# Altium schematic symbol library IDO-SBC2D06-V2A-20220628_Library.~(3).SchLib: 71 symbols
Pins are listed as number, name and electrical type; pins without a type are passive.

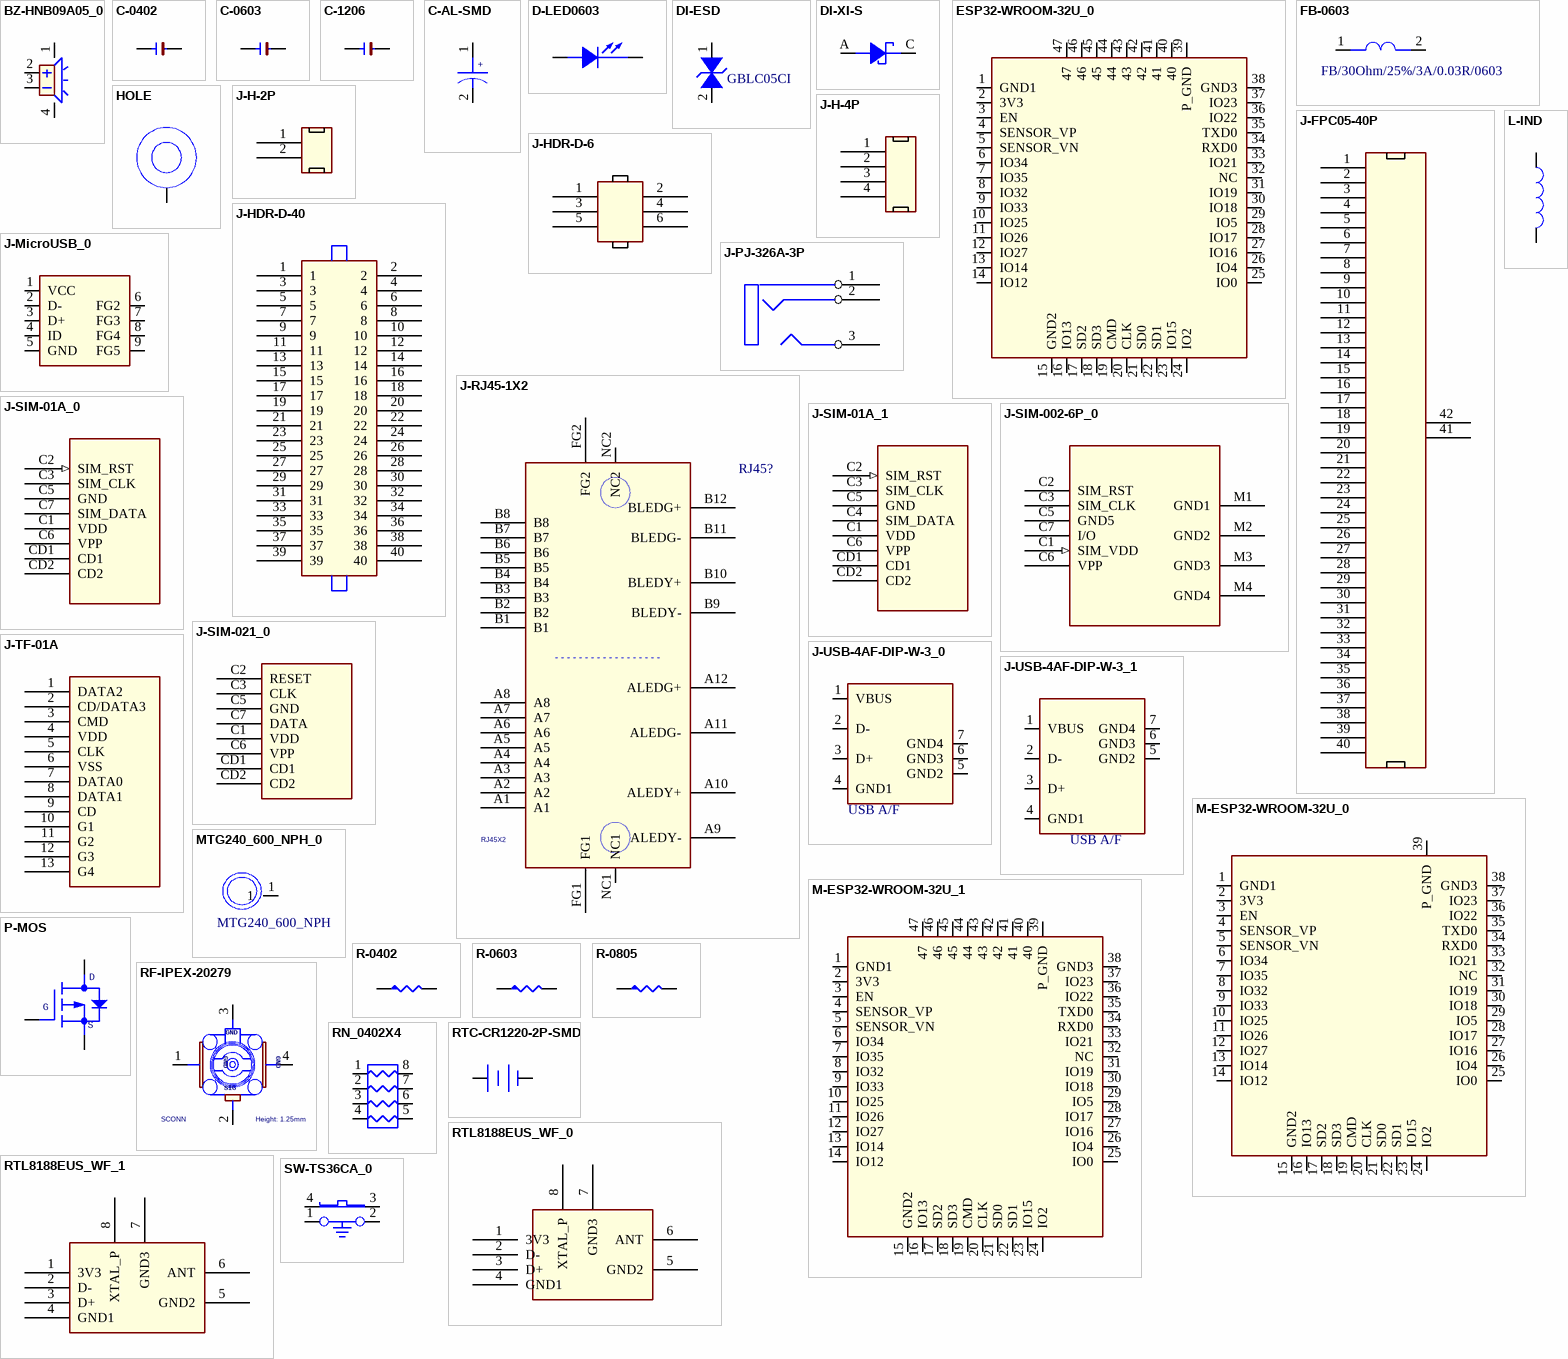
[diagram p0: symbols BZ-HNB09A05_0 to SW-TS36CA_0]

## BZ-HNB09A05_0
designator BUZZER?
Altium-Right: 20; Altium-Bottom: 30
pins: 1, 2 +, 3 -, 4

## C-0402
designator C?
Altium-Right: 10; Altium-Bottom: 20
footprint 1206
pins: 1, 2

## C-0603
designator C?
Altium-Right: 10; Altium-Bottom: 20
footprint 1206
pins: 1, 2

## C-1206
designator C?
Altium-Right: 10; Altium-Bottom: 20
footprint 1206
pins: 1, 2

## C-AL-SMD
designator CP?
Altium-Right: 20
pins: 1, 2

## D-LED0603
designator LED?
Altium-Right: 40; Altium-Bottom: 20
pins: A ANODE, C CATHODE

## DI-ESD
designator T?, comment GBLC05CI
ESD 0402; Manufacturer: INPAQ; Manufacture P/N: MLVG04021R0UV18; Part Number: EB3.1R0UV18402A; PN Type: Varistor; Altium-Right: 20
pins: 1 I/O2, 2 I/O1

## DI-XI-S
designator D?
CLASS: IC; Altium-Right: 30; Altium-Bottom: 20
pins: A, C

## ESP32-WROOM-32U_0
designator U?
Altium-Right: 170; Altium-Bottom: 200
pins: 1 GND1, 2 3V3, 3 EN, 4 SENSOR_VP, 5 SENSOR_VN, 6 IO34, 7 IO35, 8 IO32, 9 IO33, 10 IO25, 11 IO26, 12 IO27, 13 IO14, 14 IO12, 15 GND2, 16 IO13, 17 SD2, 18 SD3, 19 CMD, 20 CLK, 21 SD0, 22 SD1, 23 IO15, 24 IO2, 25 IO0, 26 IO4, 27 IO16, 28 IO17, 29 IO5, 30 IO18, 31 IO19, 32 NC, 33 IO21, 34 RXD0, 35 TXD0, 36 IO22, 37 IO23, 38 GND3, 39 P_GND, 40, 41, 42, 43, 44, 45, 46, 47

## FB-0603
designator FB?, comment FB/30Ohm/25%/3A/0.03R/0603
SMD Multilayer Ferrite Chip Bead,3A,30Ohm,0.03R; Part Number: EL4.300Y060300A; Manufacture P/N: PZ1608D300-3R0TF; Manufacture2 P/N: PBY160808T-400Y-N; Manufacturer: SUNLORD; PN Type: SMD FERRITE BEAD; Altium-Right: 40; Altium-Bottom: 20
pins: 1, 2

## HOLE
designator H?  (value not drawn)
Altium-Right: 40
pins: 1

## J-FPC05-40P
designator J?
Altium-Right: 40; Altium-Bottom: 410
pins: 1, 2, 3, 4, 5, 6, 7, 8, 9, 10, 11, 12, 13, 14, 15, 16, 17, 18, 19, 20, 21, 22, 23, 24, 25, 26, 27, 28, 29, 30, 31, 32, 33, 34, 35, 36, 37, 38, 39, 40, 41, 42

## J-H-2P
designator J?
Altium-Right: 20; Altium-Bottom: 30
pins: 1, 2

## J-H-4P
designator J?
Altium-Right: 20; Altium-Bottom: 50
pins: 1, 2, 3, 4

## J-HDR-D-6
designator J?
Altium-Right: 30; Altium-Bottom: 60
pins: 1, 2, 3, 4, 5, 6

## J-HDR-D-40
designator J?
Altium-Right: 50; Altium-Bottom: 230
pins: 1, 2, 3, 4, 5, 6, 7, 8, 9, 10, 11, 12, 13, 14, 15, 16, 17, 18, 19, 20, 21, 22, 23, 24, 25, 26, 27, 28, 29, 30, 31, 32, 33, 34, 35, 36, 37, 38, 39, 40

## J-MicroUSB_0
designator CN?  (value not drawn)
MicroUSB; Altium-Right: 60
pins: 1 VCC (power), 2 D- (power), 3 D+ (power), 4 ID (io), 5 GND (power), 6 FG2 (power), 7 FG3 (power), 8 FG4 (power), 9 FG5

## J-PJ-326A-3P
designator AU?
P/N: 182K00300S; Altium-Right: 60
pins: 1 COM, 2 L, 3 R

## J-RJ45-1X2
designator RJ45?, comment RJ45X2
Altium-Right: 110; Altium-Bottom: 270
pins: A1, A2, A3, A4, A5, A6, A7, A8, A9 ALEDY-, A10 ALEDY+, A11 ALEDG-, A12 ALEDG+, B1, B2, B3, B4, B5, B6, B7, B8, B9 BLEDY-, B10 BLEDY+, B11 BLEDG-, B12 BLEDG+, FG1, FG2, NC1, NC2

## J-SIM-01A_0
designator J?
Altium-Right: 60; Altium-Bottom: 110
pins: C1 VDD, C2 SIM_RST (in), C3 SIM_CLK, C5 GND, C6 VPP, C7 SIM_DATA, CD1, CD2

## J-SIM-01A_1
designator J?
Altium-Right: 60; Altium-Bottom: 110
pins: C1 VDD, C2 SIM_RST (in), C3 SIM_CLK, C4 SIM_DATA, C5 GND, C6 VPP, CD1, CD2

## J-SIM-002-6P_0
designator SIM?
Altium-Right: 100; Altium-Bottom: 120
pins: C1 SIM_VDD (in), C2 SIM_RST, C3 SIM_CLK, C5 GND5, C6 VPP, C7 I/O, M1 GND1, M2 GND2, M3 GND3, M4 GND4

## J-SIM-021_0
designator J?
Altium-Right: 60; Altium-Bottom: 90
pins: C1 VDD, C2 RESET, C3 CLK, C5 GND, C6 VPP, C7 DATA, CD1, CD2

## J-TF-01A
designator J?
Altium-Right: 60; Altium-Bottom: 140
pins: 1 DATA2, 2 CD/DATA3, 3 CMD, 4 VDD, 5 CLK, 6 VSS, 7 DATA0, 8 DATA1, 9 CD, 10 G1, 11 G2, 12 G3, 13 G4

## J-USB-4AF-DIP-W-3_0
designator USB?, comment USB A/F
micro USB连接器; Altium-Right: 70; Altium-Bottom: 80
pins: 1 VBUS (power), 2 D-, 3 D+, 4 GND1 (power), 5 GND2, 6 GND3, 7 GND4

## J-USB-4AF-DIP-W-3_1
designator USB?, comment USB A/F
micro USB连接器; Altium-Right: 70; Altium-Bottom: 90
pins: 1 VBUS (power), 2 D-, 3 D+, 4 GND1 (power), 5 GND2, 6 GND3, 7 GND4

## L-IND
designator L?
Altium-Right: 10; Altium-Bottom: 40
pins: 1, 2

## M-ESP32-WROOM-32U_0
designator U?
Altium-Right: 170; Altium-Bottom: 200
pins: 1 GND1, 2 3V3, 3 EN, 4 SENSOR_VP, 5 SENSOR_VN, 6 IO34, 7 IO35, 8 IO32, 9 IO33, 10 IO25, 11 IO26, 12 IO27, 13 IO14, 14 IO12, 15 GND2, 16 IO13, 17 SD2, 18 SD3, 19 CMD, 20 CLK, 21 SD0, 22 SD1, 23 IO15, 24 IO2, 25 IO0, 26 IO4, 27 IO16, 28 IO17, 29 IO5, 30 IO18, 31 IO19, 32 NC, 33 IO21, 34 RXD0, 35 TXD0, 36 IO22, 37 IO23, 38 GND3, 39 P_GND

## M-ESP32-WROOM-32U_1
designator U?
Altium-Right: 170; Altium-Bottom: 200
pins: 1 GND1, 2 3V3, 3 EN, 4 SENSOR_VP, 5 SENSOR_VN, 6 IO34, 7 IO35, 8 IO32, 9 IO33, 10 IO25, 11 IO26, 12 IO27, 13 IO14, 14 IO12, 15 GND2, 16 IO13, 17 SD2, 18 SD3, 19 CMD, 20 CLK, 21 SD0, 22 SD1, 23 IO15, 24 IO2, 25 IO0, 26 IO4, 27 IO16, 28 IO17, 29 IO5, 30 IO18, 31 IO19, 32 NC, 33 IO21, 34 RXD0, 35 TXD0, 36 IO22, 37 IO23, 38 GND3, 39 P_GND, 40, 41, 42, 43, 44, 45, 46, 47

## MTG240_600_NPH_0
designator NPV?, comment MTG240_600_NPH
Altium-Right: 27
pins: 1

## P-MOS
designator Q?
Altium-Right: 50; Altium-Bottom: 40
pins: 1 GATE, 2 SOURCE, 3 DRAIN

## R-0402
designator R?
Altium-Right: 20
pins: 1, 2

## R-0603
designator R?
Altium-Right: 20
pins: 1, 2

## R-0805
designator R?
Altium-Right: 20
pins: 1, 2

## RF-IPEX-20279
designator IPEX?  Material: SCONN  Height: 1.25mm
SMD micro Coaxial Connector Receptacle vertial; Pack_Type: MHF-20279; Altium-Right: 60
pins: 1 GND1, 2 SIG, 3 GND2, 4 GND3

## RN_0402X4
designator RN?
Altium-Right: 20; Altium-Bottom: 50
pins: 1, 2, 3, 4, 5, 6, 7, 8

## RTC-CR1220-2P-SMD
designator BAT?
Altium-Right: 20
pins: 1 +, 2 -

## RTL8188EUS_WF_0
designator U?
Altium-Right: 90; Altium-Bottom: 60
pins: 1 3V3, 2 D-, 3 D+, 4 GND1 (power), 5 GND2 (power), 6 ANT, 7 GND3, 8 XTAL_P

## RTL8188EUS_WF_1
designator U?
Altium-Right: 90; Altium-Bottom: 60
pins: 1 3V3, 2 D-, 3 D+, 4 GND1 (power), 5 GND2 (power), 6 ANT, 7 GND3, 8 XTAL_P

## SW-TS36CA_0
designator SW?
Altium-Right: 30
pins: 1, 2, 3, 4

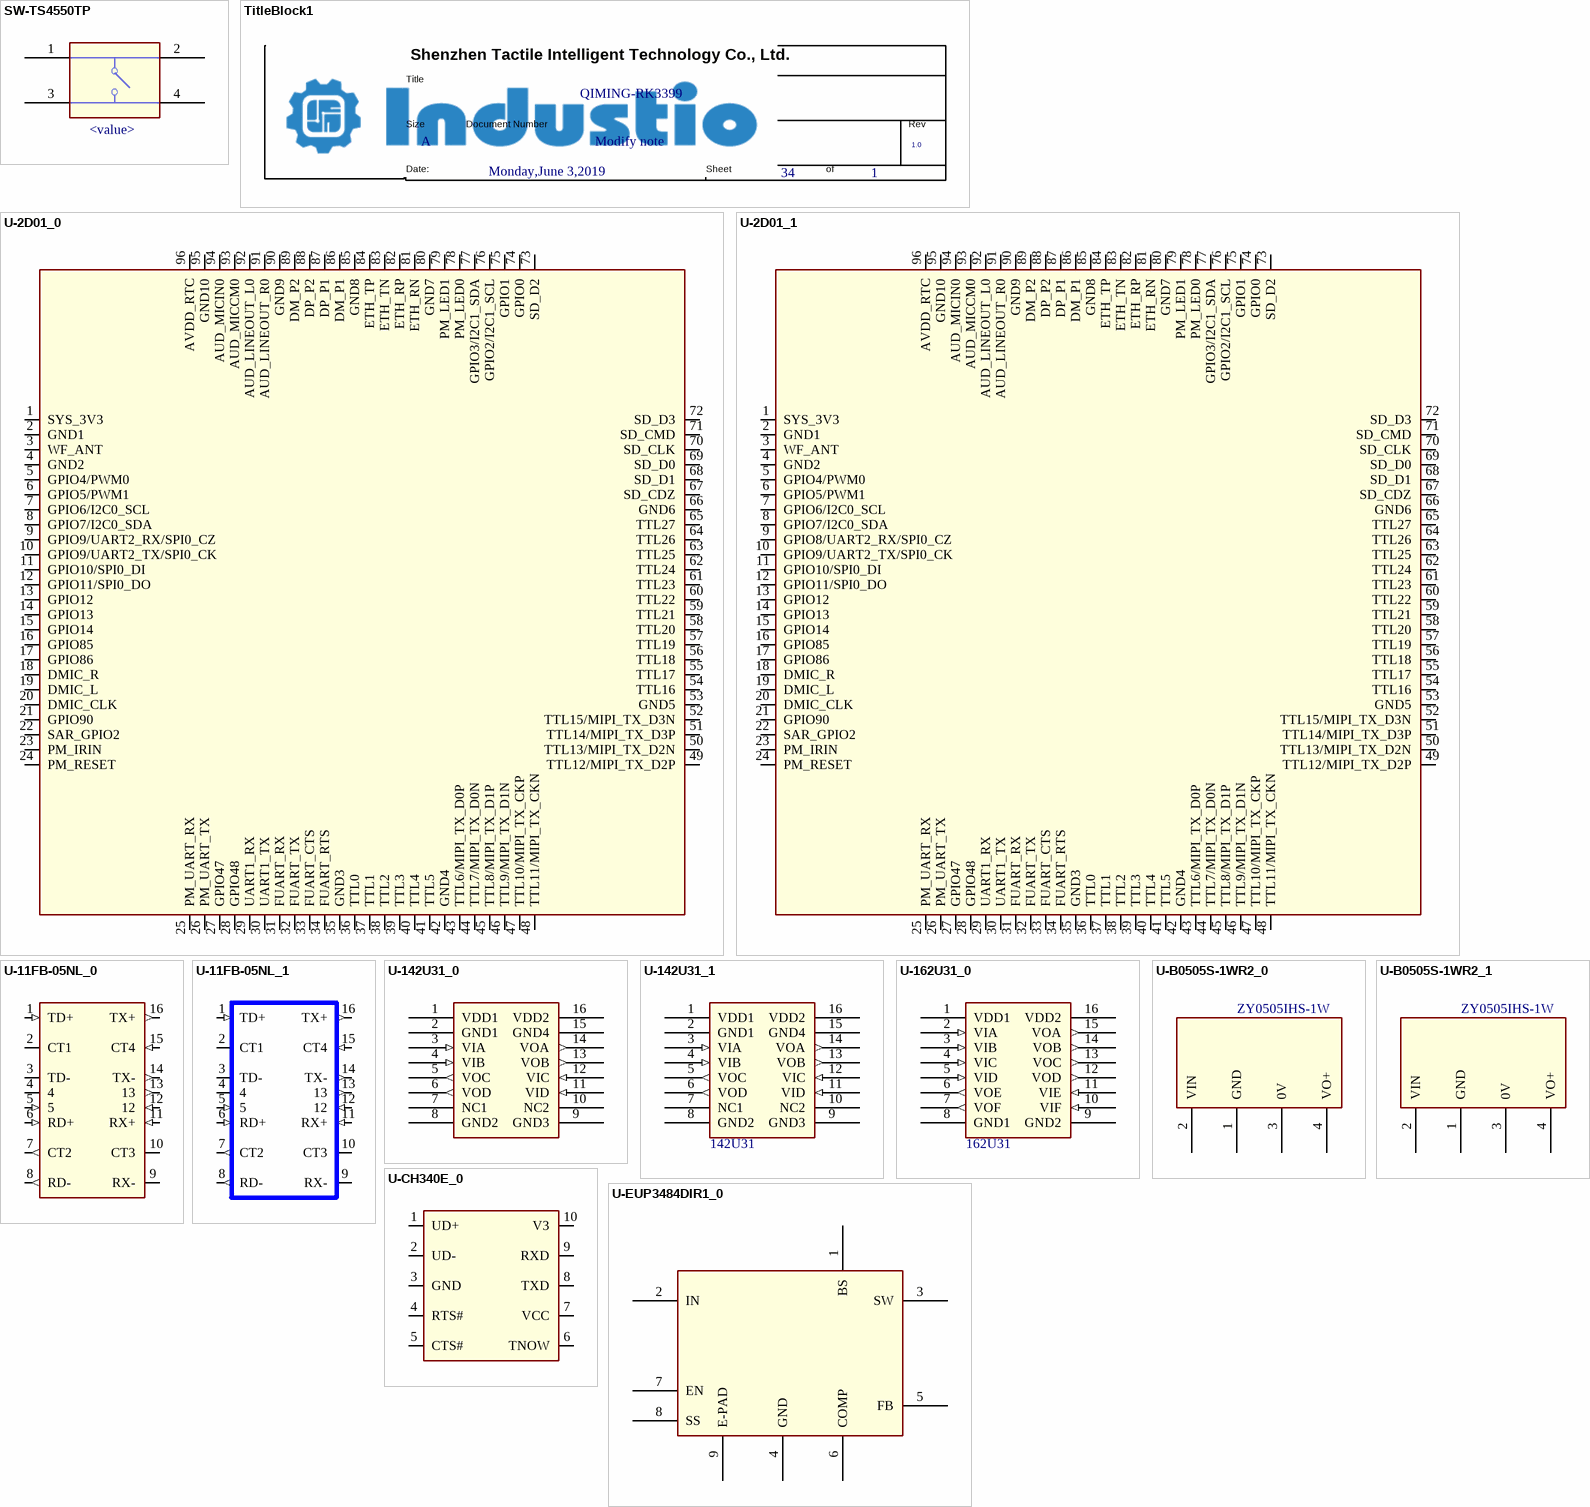
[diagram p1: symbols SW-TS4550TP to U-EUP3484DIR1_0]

## SW-TS4550TP
designator SW?, comment <value>
Altium-Right: 60; Altium-Bottom: 50
pins: 1, 2, 3, 4

## TitleBlock1
designator *  Page Count: 1  Page Number: 34  Page Size: A  Title: QIMING-RK3399  RevCode: 1.0  Doc: Modify note  Page Modify Date: Monday,June 3,2019  (hidden comment: *)  (graphical)
Altium-Right: 455; Altium-Bottom: 91

## U-2D01_0
designator U?
Altium-Right: 430
pins: 1 SYS_3V3, 2 GND1, 3 WF_ANT, 4 GND2, 5 GPIO4/PWM0, 6 GPIO5/PWM1, 7 GPIO6/I2C0_SCL, 8 GPIO7/I2C0_SDA, 9 GPIO9/UART2_RX/SPI0_CZ, 10 GPIO9/UART2_TX/SPI0_CK, 11 GPIO10/SPI0_DI, 12 GPIO11/SPI0_DO, 13 GPIO12, 14 GPIO13, 15 GPIO14, 16 GPIO85, 17 GPIO86, 18 DMIC_R, 19 DMIC_L, 20 DMIC_CLK, 21 GPIO90, 22 SAR_GPIO2, 23 PM_IRIN, 24 PM_RESET, 25 PM_UART_RX, 26 PM_UART_TX, 27 GPIO47, 28 GPIO48, 29 UART1_RX, 30 UART1_TX, 31 FUART_RX, 32 FUART_TX, 33 FUART_CTS, 34 FUART_RTS, 35 GND3, 36 TTL0, 37 TTL1, 38 TTL2, 39 TTL3, 40 TTL4, 41 TTL5, 42 GND4, 43 TTL6/MIPI_TX_D0P, 44 TTL7/MIPI_TX_D0N, 45 TTL8/MIPI_TX_D1P, 46 TTL9/MIPI_TX_D1N, 47 TTL10/MIPI_TX_CKP, 48 TTL11/MIPI_TX_CKN, 49 TTL12/MIPI_TX_D2P, 50 TTL13/MIPI_TX_D2N, 51 TTL14/MIPI_TX_D3P, 52 TTL15/MIPI_TX_D3N, 53 GND5, 54 TTL16, 55 TTL17, 56 TTL18, 57 TTL19, 58 TTL20, 59 TTL21, 60 TTL22, 61 TTL23, 62 TTL24, 63 TTL25, 64 TTL26, 65 TTL27, 66 GND6, 67 SD_CDZ, 68 SD_D1, 69 SD_D0, 70 SD_CLK, 71 SD_CMD, 72 SD_D3, 73 SD_D2, 74 GPIO0, 75 GPIO1, 76 GPIO2/I2C1_SCL, 77 GPIO3/I2C1_SDA, 78 PM_LED0, 79 PM_LED1, 80 GND7, 81 ETH_RN, 82 ETH_RP, 83 ETH_TN, 84 ETH_TP, 85 GND8, 86 DM_P1, 87 DP_P1, 88 DP_P2, 89 DM_P2, 90 GND9, 91 AUD_LINEOUT_R0, 92 AUD_LINEOUT_L0, 93 AUD_MICCM0, 94 AUD_MICIN0, 95 GND10, 96 AVDD_RTC

## U-2D01_1
designator U?
Altium-Right: 430
pins: 1 SYS_3V3, 2 GND1, 3 WF_ANT, 4 GND2, 5 GPIO4/PWM0, 6 GPIO5/PWM1, 7 GPIO6/I2C0_SCL, 8 GPIO7/I2C0_SDA, 9 GPIO8/UART2_RX/SPI0_CZ, 10 GPIO9/UART2_TX/SPI0_CK, 11 GPIO10/SPI0_DI, 12 GPIO11/SPI0_DO, 13 GPIO12, 14 GPIO13, 15 GPIO14, 16 GPIO85, 17 GPIO86, 18 DMIC_R, 19 DMIC_L, 20 DMIC_CLK, 21 GPIO90, 22 SAR_GPIO2, 23 PM_IRIN, 24 PM_RESET, 25 PM_UART_RX, 26 PM_UART_TX, 27 GPIO47, 28 GPIO48, 29 UART1_RX, 30 UART1_TX, 31 FUART_RX, 32 FUART_TX, 33 FUART_CTS, 34 FUART_RTS, 35 GND3, 36 TTL0, 37 TTL1, 38 TTL2, 39 TTL3, 40 TTL4, 41 TTL5, 42 GND4, 43 TTL6/MIPI_TX_D0P, 44 TTL7/MIPI_TX_D0N, 45 TTL8/MIPI_TX_D1P, 46 TTL9/MIPI_TX_D1N, 47 TTL10/MIPI_TX_CKP, 48 TTL11/MIPI_TX_CKN, 49 TTL12/MIPI_TX_D2P, 50 TTL13/MIPI_TX_D2N, 51 TTL14/MIPI_TX_D3P, 52 TTL15/MIPI_TX_D3N, 53 GND5, 54 TTL16, 55 TTL17, 56 TTL18, 57 TTL19, 58 TTL20, 59 TTL21, 60 TTL22, 61 TTL23, 62 TTL24, 63 TTL25, 64 TTL26, 65 TTL27, 66 GND6, 67 SD_CDZ, 68 SD_D1, 69 SD_D0, 70 SD_CLK, 71 SD_CMD, 72 SD_D3, 73 SD_D2, 74 GPIO0, 75 GPIO1, 76 GPIO2/I2C1_SCL, 77 GPIO3/I2C1_SDA, 78 PM_LED0, 79 PM_LED1, 80 GND7, 81 ETH_RN, 82 ETH_RP, 83 ETH_TN, 84 ETH_TP, 85 GND8, 86 DM_P1, 87 DP_P1, 88 DP_P2, 89 DM_P2, 90 GND9, 91 AUD_LINEOUT_R0, 92 AUD_LINEOUT_L0, 93 AUD_MICCM0, 94 AUD_MICIN0, 95 GND10, 96 AVDD_RTC

## U-11FB-05NL_0
designator U?
OriginalSymbolOrigin: (0,0); Altium-Right: 70; Altium-Bottom: 130
pins: 1 TD+ (in), 2 CT1, 3 TD-, 4, 5 (in), 6 RD+ (in), 7 CT2 (out), 8 RD- (out), 9 RX-, 10 CT3, 11 RX+ (in), 12 (in), 13 (out), 14 TX- (out), 15 CT4 (in), 16 TX+ (out)

## U-11FB-05NL_1
designator U?
OriginalSymbolOrigin: (0,0); Altium-Right: 70; Altium-Bottom: 130
pins: 1 TD+ (in), 2 CT1, 3 TD-, 4, 5 (in), 6 RD+ (in), 7 CT2 (out), 8 RD- (out), 9 RX-, 10 CT3, 11 RX+ (in), 12 (in), 13 (out), 14 TX- (out), 15 CT4 (in), 16 TX+ (out)

## U-142U31_0
designator U?
Altium-Right: 70; Altium-Bottom: 90
pins: 1 VDD1, 2 GND1, 3 VIA (in), 4 VIB (in), 5 VOC (out), 6 VOD (out), 7 NC1, 8 GND2, 9 GND3, 10 NC2, 11 VID (in), 12 VIC (in), 13 VOB (out), 14 VOA (out), 15 GND4, 16 VDD2

## U-142U31_1
designator U?, comment 142U31
Altium-Right: 70; Altium-Bottom: 90
pins: 1 VDD1, 2 GND1, 3 VIA (in), 4 VIB (in), 5 VOC (out), 6 VOD (out), 7 NC1, 8 GND2, 9 GND3, 10 NC2, 11 VID (in), 12 VIC (in), 13 VOB (out), 14 VOA (out), 15 GND4, 16 VDD2

## U-162U31_0
designator U?, comment 162U31
Altium-Right: 70; Altium-Bottom: 90
pins: 1 VDD1, 2 VIA (in), 3 VIB (in), 4 VIC (in), 5 VID (in), 6 VOE (out), 7 VOF (out), 8 GND1, 9 GND2, 10 VIF (in), 11 VIE (in), 12 VOD (out), 13 VOC (out), 14 VOB (out), 15 VOA (out), 16 VDD2

## U-B0505S-1WR2_0
designator U?, comment ZY0505IHS-1W
Altium-Right: 110; Altium-Bottom: 60
pins: 1 GND, 2 VIN, 3 0V, 4 VO+

## U-B0505S-1WR2_1
designator U?, comment ZY0505IHS-1W
Altium-Right: 110; Altium-Bottom: 60
pins: 1 GND, 2 VIN, 3 0V, 4 VO+

## U-CH340E_0
designator U?
Altium-Right: 90; Altium-Bottom: 100
pins: 1 UD+, 2 UD-, 3 GND, 4 RTS#, 5 CTS#, 6 TNOW (io), 7 VCC, 8 TXD, 9 RXD, 10 V3

## U-EUP3484DIR1_0
designator U?
Altium-Right: 150; Altium-Bottom: 110
pins: 1 BS, 2 IN, 3 SW, 4 GND, 5 FB, 6 COMP, 7 EN, 8 SS, 9 E-PAD

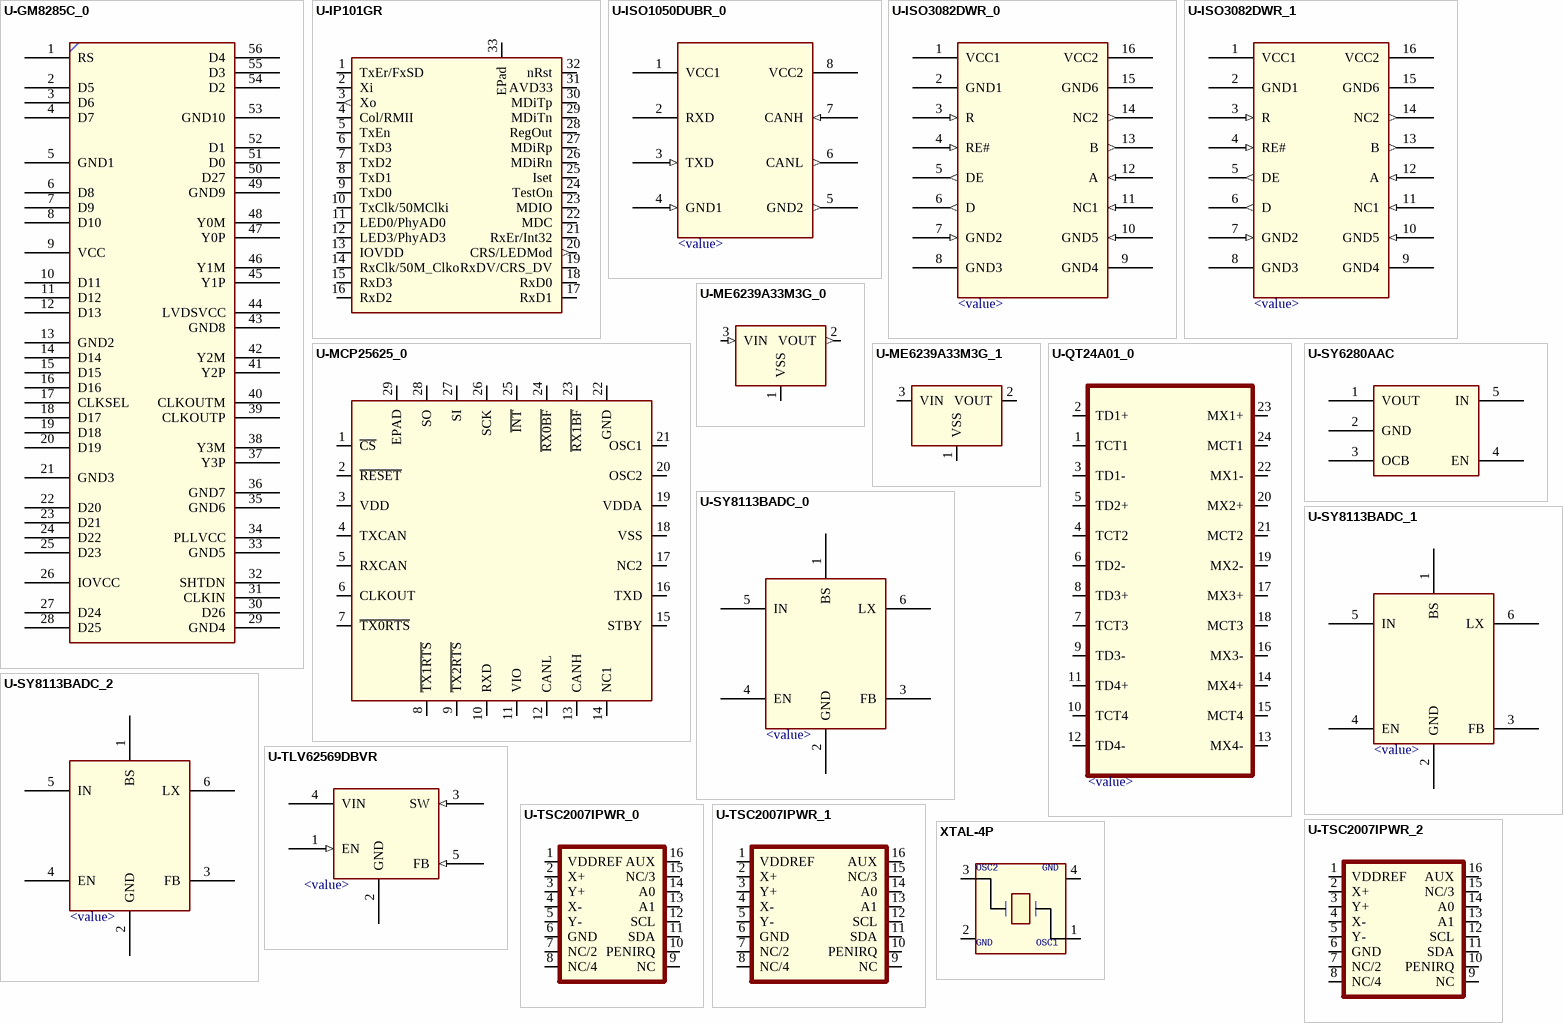
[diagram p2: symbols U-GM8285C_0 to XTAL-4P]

## U-GM8285C_0
designator U?
Altium-Right: 110; Altium-Bottom: 400
pins: 1 RS, 2 D5, 3 D6, 4 D7, 5 GND1, 6 D8, 7 D9, 8 D10, 9 VCC, 10 D11, 11 D12, 12 D13, 13 GND2, 14 D14, 15 D15, 16 D16, 17 CLKSEL, 18 D17, 19 D18, 20 D19, 21 GND3, 22 D20, 23 D21, 24 D22, 25 D23, 26 IOVCC, 27 D24, 28 D25, 29 GND4, 30 D26, 31 CLKIN, 32 SHTDN, 33 GND5, 34 PLLVCC, 35 GND6, 36 GND7, 37 Y3P, 38 Y3M, 39 CLKOUTP, 40 CLKOUTM, 41 Y2P, 42 Y2M, 43 GND8, 44 LVDSVCC, 45 Y1P, 46 Y1M, 47 Y0P, 48 Y0M, 49 GND9, 50 D27, 51 D0, 52 D1, 53 GND10, 54 D2, 55 D3, 56 D4

## U-IP101GR
designator U?
Altium-Right: 140; Altium-Bottom: 170
footprint QFN32
pins: 1 TxEr/FxSD, 2 Xi, 3 Xo (out), 4 Col/RMII, 5 TxEn, 6 TxD3, 7 TxD2, 8 TxD1, 9 TxD0, 10 TxClk/50MClki, 11 LED0/PhyAD0, 12 LED3/PhyAD3, 13 IOVDD, 14 RxClk/50M_Clko, 15 RxD3, 16 RxD2, 17 RxD1, 18 RxD0, 19 RxDV/CRS_DV, 20 CRS/LEDMod (out), 21 RxEr/Int32, 22 MDC, 23 MDIO, 24 TestOn, 25 Iset, 26 MDiRn, 27 MDiRp, 28 RegOut, 29 MDiTn, 30 MDiTp, 31 AVD33, 32 nRst, 33 EPad (power)

## U-ISO1050DUBR_0
designator U?, comment <value>
Altium-Right: 90; Altium-Bottom: 130
pins: 1 VCC1 (power), 2 RXD (power), 3 TXD (in), 4 GND1 (in), 5 GND2 (out), 6 CANL (out), 7 CANH (in), 8 VCC2 (power)

## U-ISO3082DWR_0
designator U?, comment <value>
Altium-Right: 100; Altium-Bottom: 170
pins: 1 VCC1 (power), 2 GND1 (power), 3 R (in), 4 RE# (in), 5 DE (out), 6 D (out), 7 GND2 (in), 8 GND3 (power), 9 GND4 (power), 10 GND5 (in), 11 NC1 (in), 12 A (in), 13 B (out), 14 NC2 (out), 15 GND6 (power), 16 VCC2 (power)

## U-ISO3082DWR_1
designator U?, comment <value>
Altium-Right: 90; Altium-Bottom: 170
pins: 1 VCC1 (power), 2 GND1 (power), 3 R (in), 4 RE# (in), 5 DE (out), 6 D (out), 7 GND2 (in), 8 GND3 (power), 9 GND4 (power), 10 GND5 (in), 11 NC1 (in), 12 A (in), 13 B (out), 14 NC2 (out), 15 GND6 (power), 16 VCC2 (power)

## U-MCP25625_0
designator U?
Altium-Right: 200
pins: 1 ~{CS}, 2 ~{RESET}, 3 VDD, 4 TXCAN, 5 RXCAN, 6 CLKOUT, 7 ~{TX0RTS}, 8 ~{TX1RTS}, 9 ~{TX2RTS}, 10 RXD, 11 VIO, 12 CANL, 13 CANH, 14 NC1, 15 STBY, 16 TXD, 17 NC2, 18 VSS, 19 VDDA, 20 OSC2, 21 OSC1, 22 GND, 23 ~{RX1BF}, 24 ~{RX0BF}, 25 ~{INT}, 26 SCK, 27 SI, 28 SO, 29 EPAD

## U-ME6239A33M3G_0
designator U?
Altium-Right: 60; Altium-Bottom: 40
pins: 1 VSS (power), 2 VOUT (out), 3 VIN (in)

## U-ME6239A33M3G_1
designator U?
Altium-Right: 60; Altium-Bottom: 40
pins: 1 VSS, 2 VOUT, 3 VIN

## U-QT24A01_0
designator U?, comment <value>
Altium-Right: 110; Altium-Bottom: 260
pins: 1 TCT1, 2 TD1+, 3 TD1-, 4 TCT2, 5 TD2+, 6 TD2-, 7 TCT3, 8 TD3+, 9 TD3-, 10 TCT4, 11 TD4+, 12 TD4-, 13 MX4-, 14 MX4+, 15 MCT4, 16 MX3-, 17 MX3+, 18 MCT3, 19 MX2-, 20 MX2+, 21 MCT2, 22 MX1-, 23 MX1+, 24 MCT1

## U-SY6280AAC
designator U?
Altium-Right: 70; Altium-Bottom: 60
pins: 1 VOUT, 2 GND, 3 OCB, 4 EN, 5 IN

## U-SY8113BADC_0
designator U?, comment <value>
Altium-Right: 80; Altium-Bottom: 100
pins: 1 BS, 2 GND, 3 FB, 4 EN, 5 IN, 6 LX

## U-SY8113BADC_1
designator U?, comment <value>
Altium-Right: 80; Altium-Bottom: 100
pins: 1 BS, 2 GND, 3 FB, 4 EN, 5 IN, 6 LX

## U-SY8113BADC_2
designator U?, comment <value>
Altium-Right: 80; Altium-Bottom: 100
pins: 1 BS, 2 GND, 3 FB, 4 EN, 5 IN, 6 LX

## U-TLV62569DBVR
designator U?, comment <value>
Altium-Right: 70; Altium-Bottom: 60
pins: 1 EN (in), 2 GND (power), 3 SW (in), 4 VIN (power), 5 FB (in)

## U-TSC2007IPWR_0
designator U?
Altium-Right: 70; Altium-Bottom: 90
pins: 1 VDDREF, 2 X+, 3 Y+, 4 X-, 5 Y-, 6 GND, 7 NC/2, 8 NC/4, 9 NC, 10 PENIRQ, 11 SDA, 12 SCL, 13 A1, 14 A0, 15 NC/3, 16 AUX

## U-TSC2007IPWR_1
designator U?
Altium-Right: 90
pins: 1 VDDREF, 2 X+, 3 Y+, 4 X-, 5 Y-, 6 GND, 7 NC/2, 8 NC/4, 9 NC, 10 PENIRQ, 11 SDA, 12 SCL, 13 A1, 14 A0, 15 NC/3, 16 AUX

## U-TSC2007IPWR_2
designator U?
Altium-Right: 80; Altium-Bottom: 90
pins: 1 VDDREF, 2 X+, 3 Y+, 4 X-, 5 Y-, 6 GND, 7 NC/2, 8 NC/4, 9 NC, 10 PENIRQ, 11 SDA, 12 SCL, 13 A1, 14 A0, 15 NC/3, 16 AUX

## XTAL-4P
designator XT?
CLASS: IC; Altium-Right: 60
pins: 1, 2, 3, 4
